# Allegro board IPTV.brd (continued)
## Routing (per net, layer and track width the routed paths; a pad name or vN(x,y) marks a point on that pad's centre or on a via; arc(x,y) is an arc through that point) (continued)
DDRB_DQ10: length 41.3
  TOP w0.127: IC13.B20 73.16,26.36 73.16,24.41
  TOP w0.152: U10.A7 55.33,10.21 55.52,10.02 57.08,10.02 v2(57.51,9.59) ; v1(71.43,15.89) 71.43,16.9 72.02,17.5 73.16,18.63 73.16,24.41
  BOTTOM w0.152: v2(57.51,9.59) 67.74,9.59 67.92,9.77 67.92,10.67 68.1,10.86 68.35,10.86 68.53,10.68 68.53,9.77 68.71,9.59 68.96,9.59 69.14,9.77 69.14,11.89 69.32,12.08 69.57,12.08 69.75,11.9 69.75,9.77 69.93,9.59 70.18,9.59 70.36,9.77 70.36,13.11 70.36,13.11 70.36,13.45 70.36,14.96 71.29,15.89 v1(71.43,15.89)
DDRB_DQ11: length 40.5
  TOP w0.127: 72.75,24.41 IC13.A20
  TOP w0.152: U10.D7 52.12,10.21 v2(52.52,10.61) ; 71.21,17.26 72.75,18.8 72.75,24.41 ; 71.21,17.26 71.49,17.54 ; 71.21,17.26 v1(70.46,16.51)
  BOTTOM w0.152: v2(52.52,10.61) 52.58,10.54 66.64,10.54 69.55,13.45 69.55,19.85 69.8,20.1 70.21,20.1 70.46,19.85 v1(70.46,16.51)
DDRB_DQ12: length 44.4
  TOP w0.127: 70.82,24.28 70.82,25 70.76,25.06 70.76,25.78 70.75,25.8 70.75,26.37 IC13.B23
  TOP w0.152: 70.82,24.28 70.82,19.6 66.32,15.1 64.29,15.1 64.11,14.92 64.11,14.03 63.93,13.85 63.68,13.85 63.5,14.03 63.5,14.92 63.32,15.1 63.07,15.1 62.89,14.92 62.89,14.03 62.71,13.85 61.65,13.85 61.47,14.03 61.47,14.92 61.29,15.1 61.04,15.1 60.86,14.92 60.86,14.03 60.68,13.85 59.61,13.85 59.44,14.03 59.44,14.95 59.28,15.1 58.98,15.1 58.83,14.95 58.83,13.25 58.59,13.01 57.64,13.01 57.4,13.25 57.4,16.63 57.4,18.68 57.15,18.94 56.39,18.94 56.13,18.68 56.13,13.78 55.77,13.41 U10.A3
DDRB_DQ13: length 44.4
  TOP w0.127: IC13.C23 69.96,27.18 69.96,25.65 70.01,25.61 70.01,24.28
  TOP w0.152: U10.A2 55.09,14.21 55.32,14.44 55.32,17.89 55.07,18.15 53.59,18.15 53.44,18.3 53.44,18.6 53.6,18.76 55.14,18.76 55.32,18.94 55.32,19.19 55.14,19.37 51.99,19.37 51.82,19.54 51.82,19.8 52,19.98 57.94,19.98 58.22,19.7 58.22,16.12 58.42,15.91 65.98,15.91 70.01,19.94 70.01,24.28
DDRB_DQ14: length 43
  TOP w0.102: U10.C3 53.32,13.82 55.36,13.82 55.55,14.01
  TOP w0.127: IC13.A23 70.42,25.9 70.42,24.28
  TOP w0.152: 70.42,24.28 70.42,19.77 66.15,15.51 62.71,15.51 62.48,15.28 62.48,14.44 62.31,14.26 62.05,14.26 61.87,14.44 61.87,15.33 61.7,15.51 60.63,15.51 60.45,15.33 60.45,14.44 60.27,14.26 60.02,14.26 59.84,14.44 59.84,15.33 59.66,15.51 58.6,15.51 58.42,15.33 58.42,13.57 58.27,13.42 57.96,13.42 57.81,13.57 57.81,16.8 57.81,19.32 57.56,19.57 55.96,19.57 55.73,19.34 55.73,14.19 55.55,14.01
DDRB_DQ15: length 44.2
  TOP w0.102: U10.C2 52.95,14.21 53.32,14.59 53.32,15.27
  TOP w0.127: IC13.C24 69.6,27.52 69.6,24.28
  TOP w0.152: 53.32,15.27 53.32,16.12 53.65,16.45 54.69,16.45 54.92,16.67 54.92,17.54 54.71,17.74 51.56,17.74 51.41,17.89 51.41,18.2 51.56,18.35 52.68,18.35 52.83,18.5 52.83,18.81 52.68,18.96 51.66,18.96 51.41,19.22 51.41,20.15 51.64,20.38 58.32,20.38 58.62,20.08 58.62,16.55 58.85,16.32 65.81,16.32 69.6,20.11 69.6,24.28
DDRB_DQSN0: length 44.8
  TOP w0.127: 74.89,24.31 74.85,24.35 74.85,25.2 74.76,25.29 74.76,27.73 74.35,28.14 IC13.D18
  TOP w0.152: 74.89,24.31 74.89,17.85 70.04,13 67.3,13 66.88,12.59 66.88,10.07 66.28,9.47 63.77,9.47 63.22,10.02 63.22,12.18 62.87,12.53 60.07,12.53 59.23,11.69 50.85,11.69 49.96,12.58 49.96,13.16 U10.G3
DDRB_DQSN1: length 41.8
  TOP w0.127: 72.14,24.31 72.14,27.1 71.95,27.29 IC13.C21
  TOP w0.152: v1(68.07,14.37) 67.84,14.59 67.84,14.75 72.14,19.06 72.14,24.31 ; v1(62.61,11.16) 62.38,11.39 61.87,11.39 61.64,11.17 61.64,10.98 61.42,10.76 61.11,10.76 60.88,10.98 60.88,11.17 60.66,11.39 60.22,11.39 59.61,10.78 53.56,10.78 53.37,10.58 53.37,10.35 53.5,10.21 U10.B7
  BOTTOM w0.152: v1(62.61,11.16) 62.84,11.39 63.17,11.39 63.49,11.71 63.49,13.73 63.71,13.96 64.02,13.96 64.25,13.73 64.25,11.56 64.65,11.16 65.22,11.16 65.62,11.56 65.62,13.73 65.84,13.96 66.16,13.96 66.38,13.73 66.38,12.73 66.78,12.33 67.46,12.33 67.84,12.71 67.84,14.14 v1(68.07,14.37)
DDRB_DQSP0: length 44.8
  TOP w0.127: IC13.C18 74.53,27.39 74.53,25.19 74.62,25.11 74.62,24.35 74.58,24.31
  TOP w0.152: U10.F3 50.27,13.16 50.27,12.71 50.98,11.99 59.1,11.99 59.95,12.84 62.99,12.84 63.53,12.3 63.53,10.15 63.9,9.77 66.15,9.77 66.57,10.2 66.57,12.71 67.17,13.31 69.92,13.31 70.21,13.6 70.21,13.91 69.67,14.45 69.67,14.77 69.89,14.99 70.21,14.99 70.75,14.45 71.06,14.45 74.58,17.97 74.58,24.31
DDRB_DQSP1: length 41.9
  TOP w0.127: 71.84,24.31 71.84,27.06 71.56,27.34 71.56,27.98 IC13.D21
  TOP w0.152: U10.C7 53.06,10.36 53.06,10.71 53.44,11.08 59.48,11.08 60.1,11.7 62.38,11.7 v1(62.61,11.92) ; 71.84,24.31 71.84,19.18 67.54,14.88 67.54,14.59 v1(67.31,14.37)
  BOTTOM w0.152: v1(67.31,14.37) 67.54,14.13 67.54,12.84 67.34,12.64 66.9,12.64 66.69,12.85 66.69,13.86 66.28,14.26 65.72,14.26 65.31,13.86 65.31,11.69 65.09,11.47 64.78,11.47 64.55,11.69 64.55,13.86 64.15,14.26 63.58,14.26 63.18,13.86 63.18,11.83 63.05,11.7 62.84,11.7 v1(62.61,11.92)
DDRB_ODT0: length 31.9
  TOP w0.152: R285.1 v1(49.67,28.07) ; v1(48.87,22.01) 48.87,21.63 48.11,20.87 48.11,16.81 47.31,16.02 U10.K1
  BOTTOM w0.152: v1(48.87,22.01) 48.87,22.31 49.07,22.52 52.6,22.52 52.78,22.69 52.78,23.76 52.6,23.94 48.59,23.94 48.41,24.12 48.41,24.37 48.59,24.55 52.55,24.55 52.81,24.8 52.81,27.82 52.56,28.07 v1(49.67,28.07)
DDRB_ODT0_R: length 7.4
  TOP w0.127: IC13.D35 60.35,27.96 59.32,27.96 58.89,27.96 58.63,27.7 58.54,27.61 57.06,27.61 57.02,27.64
  TOP w0.152: 57.02,27.64 56.6,28.07 R285.2
DDRB_RASN: length 33.8
  TOP w0.102: 48.51,16.64 48.51,13.81 U10.J3
  TOP w0.152: R274.1 49.33,29.21 v1(49,28.88) ; v1(49.51,22.01) 49.51,21.69 48.51,20.7 48.51,16.64
  BOTTOM w0.152: 49.33,22.01 v1(49.51,22.01) 53.68,22.01 53.87,22.2 53.87,22.61 53.7,22.78 53.38,22.78 53.21,22.95 53.21,23.24 53.38,23.41 53.7,23.41 53.87,23.59 53.87,23.84 53.7,24.02 53.38,24.02 53.21,24.18 53.21,24.43 53.41,24.63 53.7,24.63 53.87,24.8 53.87,25.06 53.7,25.24 53.38,25.24 53.21,25.4 53.21,25.65 53.41,25.85 53.7,25.85 53.87,26.02 53.87,26.28 53.7,26.46 53.38,26.46 53.21,26.62 53.21,26.87 53.41,27.06 53.7,27.06 53.87,27.24 53.87,27.5 53.7,27.67 53.38,27.67 53.21,27.84 53.21,28.09 53.41,28.28 53.7,28.28 53.87,28.46 53.87,28.71 53.7,28.89 49.01,28.89 v1(49,28.88)
DDRB_RASN_R: length 4.9
  TOP w0.152: IC13.D38 58.1,28.37 57.25,29.21 R274.2
DDRB_REF\G: length 11
  TOP w0.381: v2(66.75,34.37) 66.93,34.54 67.38,34.54 IC13.L26 ; IC13.L23 70.35,33.96 v2(69.95,33.56) ; IC13.L21 71.95,33.97 71.55,34.36 v2(71.55,34.36)
  BOTTOM w0.381: C314.2 R198.2 67.47,34.37 v2(66.75,34.37)
  BOTTOM w0.406: C314.2 69.22,33.82 C315.1 69.26,32.87 v2(69.95,33.56) 70.04,33.56 C309.2 70.74,33.55 v2(71.55,34.36) 71.6,34.32 R199.1
DDRB_RESETN\G: length 32
  BOTTOM w0.152: R636.1 R637.2 38.99,28.38 39.94,29.34 55.12,29.34 58.27,26.19 R193.2
DDRB_VREF_CA: length 10.8
  TOP w0.356: v2(46.11,9.81) U10.M8
  BOTTOM w0.508: R639.2 R640.1 50.75,6.2 C472.2 49.48,6.07 C471.1 C469.1 C470.1 46.11,6.08 v2(46.11,9.81)
DDRB_VREF_DQ: length 7.9
  TOP w0.356: U10.H1 48.91,15.01 v2(48.91,15.66)
  BOTTOM w0.508: R646.1 R634.2 C474.1 C475.1 C478.1 C481.2 48.91,15.85 v2(48.91,15.66)
DDRB_WEN: length 34.5
  TOP w0.152: U10.L3 46.92,13 48.49,13 v2(48.5,13) ; v1(62.59,18) 62.64,18.05 65.24,18.05 66.93,19.73 R279.1
  BOTTOM w0.152: v1(62.59,18) 62.59,17.16 62.33,16.9 59.03,16.9 58.74,16.61 58.74,13.18 58.56,13 58.31,13 58.13,13.18 58.13,17 57.95,17.18 57.7,17.18 57.52,17 57.52,13.26 57.26,13 54.45,13 53.95,13.5 52.96,13.5 52.46,13 v2(48.5,13)
DDRB_WEN_R: length 6
  TOP w0.152: R279.2 66.93,26.19 IC13.B28
DIFF_HDMI_0N\G: length 82.9
  TOP w0.152: XP1.9 44,118.02 arc(43.95,117.79) 43.83,117.6 arc(43.7,117.41) 43.65,117.18 43.65,114.31 arc(43.71,114.04) 43.86,113.81 v1(43.88,113.79) 43.79,113.7 arc(43.69,113.55) 43.65,113.37 arc(43.69,113.21) 43.78,113.07 44.11,112.73 arc(44.31,112.44) 44.37,112.1 44.37,109.38 arc(44.45,109) 44.67,108.67 60.19,93.15 arc(60.41,92.82) 60.48,92.44 60.48,91.99 arc(60.56,91.8) 60.75,91.73 60.96,91.73 arc(61.72,90.96) 60.96,90.2 60.75,90.2 arc(60.56,90.12) 60.48,89.93 60.48,89.75 arc(60.52,89.58) 60.62,89.43 61.48,88.57 61.79,88.26 71.44,78.61 arc(71.63,78.32) 71.7,77.97 71.7,55.65 arc(71.64,55.34) 71.47,55.08 IC13.AU22
  BOTTOM w0.152: U15.9 U15.2 41.59,112.39 arc(41.66,112.4) 41.71,112.44 arc(41.76,112.47) 41.83,112.48 43.03,112.48 arc(43.47,112.67) 43.65,113.11 43.65,113.56 arc(43.72,113.73) v1(43.88,113.79)
DIFF_HDMI_0P\G: length 82.3
  TOP w0.152: XP1.7 43,117.99 arc(43.05,117.76) 43.17,117.57 arc(43.3,117.38) 43.35,117.15 43.35,114.31 arc(43.29,114.04) 43.14,113.81 v1(43.12,113.79) 43.21,113.7 arc(43.31,113.55) 43.35,113.37 arc(43.4,113.09) 43.56,112.85 43.9,112.52 arc(44.02,112.33) 44.07,112.1 44.07,109.38 arc(44.17,108.88) 44.45,108.45 59.98,92.93 arc(60.13,92.71) 60.18,92.44 60.18,91.99 arc(60.35,91.59) 60.75,91.42 60.96,91.42 arc(61.42,90.96) 60.96,90.51 60.75,90.51 arc(60.35,90.34) 60.18,89.93 60.18,89.75 arc(60.24,89.46) 60.4,89.22 61.27,88.35 61.57,88.05 65.8,83.81 arc(65.9,83.67) 65.93,83.5 65.93,83.48 arc(65.97,83.27) 66.09,83.1 66.13,83.06 arc(66.27,82.96) 66.43,82.93 66.48,82.93 arc(66.67,82.89) 66.83,82.78 arc(66.93,82.64) 66.96,82.47 66.96,82.45 arc(67,82.24) 67.12,82.07 67.16,82.03 arc(67.3,81.93) 67.46,81.9 67.51,81.9 arc(67.7,81.86) 67.86,81.75 arc(67.96,81.61) 67.99,81.44 67.99,81.42 arc(68.03,81.21) 68.15,81.04 68.19,81 arc(68.33,80.9) 68.49,80.87 68.54,80.87 arc(68.73,80.83) 68.89,80.72 arc(68.99,80.58) 69.02,80.41 69.02,80.39 arc(69.06,80.18) 69.18,80.01 69.22,79.97 arc(69.36,79.87) 69.52,79.84 69.57,79.84 arc(69.76,79.8) 69.92,79.69 arc(70.02,79.55) 70.05,79.38 70.05,79.36 arc(70.09,79.15) 70.21,78.98 70.25,78.94 arc(70.39,78.84) 70.55,78.81 70.6,78.81 arc(70.79,78.77) 70.95,78.66 71.22,78.4 arc(71.35,78.2) 71.4,77.97 71.4,56.12 arc(71.34,55.84) 71.18,55.6 IC13.AV22
  BOTTOM w0.152: U15.10 U15.1 41.59,112.89 arc(41.66,112.87) 41.71,112.84 arc(41.76,112.8) 41.83,112.79 43.03,112.79 arc(43.25,112.88) 43.35,113.11 43.35,113.56 arc(43.28,113.73) v1(43.12,113.79)
DIFF_HDMI_1N\G: length 80.6
  TOP w0.127: IC13.AU23 70.53,54.94 arc(70.69,55.18) 70.74,55.46 70.74,55.72 arc(70.7,55.92) 70.59,56.09 arc(70.5,56.22) 70.47,56.37 70.47,56.76 70.48,56.77
  TOP w0.152: XP1.6 42.5,118.07 arc(42.45,117.84) 42.33,117.65 arc(42.2,117.46) 42.15,117.23 42.15,113.4 arc(42.21,113.13) 42.36,112.9 42.78,112.48 42.92,112.34 arc(43.09,112.08) 43.15,111.77 43.15,111.57 arc(42.98,111.16) 42.57,110.98 arc(42.51,110.97) 42.47,110.94 v1(42.28,110.76) 42.15,110.89 arc(42.01,110.98) 41.84,111.02 arc(41.75,110.98) 41.71,110.88 41.71,110.15 arc(41.77,109.83) 41.95,109.56 58.2,93.31 arc(58.8,92.41) 59.01,91.35 59.01,89.88 arc(59.28,88.53) 60.04,87.39 60.15,87.29 70.13,77.31 arc(70.39,76.91) 70.48,76.44 70.48,56.77
  BOTTOM w0.152: U15.6 U15.5 41.46,110.89 arc(41.53,110.9) 41.58,110.94 arc(41.64,110.97) 41.7,110.98 42.05,110.98 arc(42.21,110.92) v1(42.28,110.76)
DIFF_HDMI_1P\G: length 80.6
  TOP w0.127: IC13.AV23 70.35,55.86 arc(70.33,55.99) 70.25,56.1 arc(70.21,56.23) 70.19,56.37 70.19,56.74 70.18,56.75 70.18,56.77
  TOP w0.152: XP1.4 41.5,118.04 arc(41.55,117.81) 41.67,117.62 arc(41.8,117.43) 41.85,117.2 41.85,113.4 arc(41.92,113.01) 42.14,112.68 42.14,112.68 42.71,112.12 arc(42.81,111.96) 42.85,111.77 42.85,111.57 arc(42.77,111.37) 42.57,111.29 arc(42.51,111.3) 42.47,111.33 v1(42.28,111.52) 42.26,111.5 arc(42.07,111.37) 41.84,111.32 arc(41.53,111.19) 41.4,110.88 41.4,110.15 arc(41.49,109.71) 41.73,109.35 57.98,93.1 arc(58.52,92.29) 58.71,91.35 58.71,89.88 arc(59,88.42) 59.82,87.18 63.53,83.47 arc(63.64,83.31) 63.68,83.12 63.68,83.07 arc(63.71,82.91) 63.8,82.77 63.84,82.73 arc(64.02,82.61) 64.22,82.57 64.25,82.57 arc(64.42,82.54) 64.56,82.44 arc(64.67,82.28) 64.71,82.09 64.71,82.04 arc(64.74,81.88) 64.83,81.74 64.87,81.7 arc(65.05,81.58) 65.25,81.54 65.28,81.54 arc(65.45,81.51) 65.59,81.41 arc(65.7,81.25) 65.74,81.06 65.74,81.01 arc(65.77,80.85) 65.86,80.71 65.9,80.67 arc(66.08,80.55) 66.28,80.51 66.31,80.51 arc(66.48,80.48) 66.62,80.38 arc(66.73,80.22) 66.77,80.03 66.77,79.98 arc(66.8,79.82) 66.89,79.68 66.93,79.64 arc(67.11,79.52) 67.31,79.48 67.34,79.48 arc(67.51,79.45) 67.65,79.35 arc(67.76,79.19) 67.8,79 67.8,78.95 arc(67.83,78.79) 67.92,78.65 67.96,78.61 arc(68.14,78.49) 68.34,78.45 68.37,78.45 arc(68.54,78.42) 68.68,78.32 arc(68.79,78.16) 68.83,77.97 68.83,77.92 arc(68.86,77.76) 68.95,77.62 68.99,77.58 arc(69.17,77.46) 69.37,77.42 69.4,77.42 arc(69.57,77.39) 69.71,77.29 69.91,77.09 arc(70.11,76.79) 70.18,76.44 70.18,56.77
  BOTTOM w0.152: U15.7 U15.4 41.44,111.39 arc(41.5,111.37) 41.55,111.34 arc(41.61,111.3) 41.67,111.29 42.05,111.29 arc(42.21,111.36) v1(42.28,111.52)
DIFF_HDMI_2N\G: length 83
  TOP w0.127: 69.27,56.77 69.25,56.76 69.25,56.36 69.42,56.2 69.42,54.28 arc(69.46,54.11) IC13.AT24
  TOP w0.152: 69.27,56.77 69.27,73.95 arc(69.03,75.15) 68.35,76.16 67.12,77.39 arc(67.03,77.53) 66.99,77.7 66.99,77.73 arc(66.95,77.93) 66.84,78.11 66.8,78.15 arc(66.66,78.24) 66.49,78.27 66.45,78.27 arc(66.26,78.31) 66.09,78.42 arc(66,78.56) 65.96,78.73 65.96,78.76 arc(65.92,78.96) 65.81,79.14 65.77,79.18 arc(65.63,79.27) 65.46,79.3 65.42,79.3 arc(65.23,79.34) 65.06,79.45 arc(64.97,79.59) 64.93,79.76 64.93,79.79 arc(64.89,79.99) 64.78,80.17 64.74,80.21 arc(64.6,80.3) 64.43,80.33 64.39,80.33 arc(64.2,80.37) 64.03,80.48 arc(63.94,80.62) 63.9,80.79 63.9,80.82 arc(63.86,81.02) 63.75,81.2 63.71,81.24 arc(63.57,81.33) 63.4,81.36 63.36,81.36 arc(63.16,81.4) 63,81.51 arc(62.91,81.65) 62.87,81.82 62.87,81.85 arc(62.83,82.05) 62.72,82.23 62.68,82.27 arc(62.54,82.36) 62.37,82.39 62.33,82.39 arc(62.13,82.43) 61.97,82.54 57.86,86.65 arc(57.6,87.04) 57.51,87.51 57.51,88.61 arc(57.32,89.05) 56.89,89.23 56.71,89.23 arc(56.52,89.31) 56.44,89.5 56.44,89.87 arc(56.52,90.06) 56.71,90.14 56.88,90.14 arc(57.29,90.31) 57.46,90.72 57.46,91.78 arc(57.36,92.24) 57.11,92.63 40.87,108.87 arc(40.71,109.1) 40.65,109.38 40.65,116.7 arc(40.7,116.95) 40.85,117.17 v1(40.88,117.2) 40.77,117.31 arc(40.68,117.44) 40.65,117.59 arc(40.66,117.65) 40.69,117.69 40.86,117.86 arc(40.96,118.01) 41,118.2 XP1.3
  BOTTOM w0.152: U16.9 U16.2 41.66,115.79 arc(41.65,115.86) 41.62,115.91 arc(41.58,115.96) 41.57,116.03 41.57,116.17 arc(41.44,116.46) 41.15,116.59 40.8,116.59 arc(40.7,116.63) 40.65,116.74 40.65,116.97 arc(40.72,117.13) v1(40.88,117.2)
DIFF_HDMI_2P\G: length 83
  TOP w0.127: IC13.AR24 69.32,53.4 arc(69.19,53.6) 69.14,53.82 69.14,56.08 68.97,56.25 68.97,56.74 68.96,56.75 68.96,56.77
  TOP w0.152: XP1.1 40,118.25 arc(40.04,118.04) 40.16,117.87 40.29,117.74 arc(40.33,117.67) 40.35,117.59 arc(40.32,117.44) 40.23,117.31 v1(40.12,117.2) 40.15,117.17 arc(40.3,116.95) 40.35,116.7 40.35,109.38 arc(40.43,108.99) 40.65,108.65 56.89,92.41 arc(57.08,92.12) 57.15,91.78 57.15,90.72 arc(57.07,90.53) 56.88,90.45 56.71,90.45 arc(56.3,90.28) 56.13,89.87 56.13,89.5 arc(56.3,89.09) 56.71,88.92 56.89,88.92 arc(57.11,88.83) 57.2,88.61 57.2,87.51 arc(57.32,86.93) 57.65,86.44 68.14,75.94 arc(68.75,75.03) 68.96,73.95 68.96,56.77
  BOTTOM w0.152: U16.10 U16.1 41.16,115.82 arc(41.18,115.89) 41.21,115.94 arc(41.25,115.99) 41.26,116.06 41.26,116.17 arc(41.23,116.25) 41.15,116.28 40.8,116.28 arc(40.48,116.42) 40.35,116.74 40.35,116.97 arc(40.28,117.13) v1(40.12,117.2)
DIFF_HDMI_CLKN\G: length 84.7
  TOP w0.127: IC13.AR21 72.14,53.35 arc(72.29,53.58) 72.34,53.85 72.34,55.62 arc(72.38,55.77) 72.46,55.9 72.66,56.1 arc(72.85,56.37) 72.91,56.7 72.91,56.74 72.92,56.75 72.92,56.77
  TOP w0.152: 72.92,56.77 72.92,78.84 arc(72.82,79.37) 72.52,79.82 64.77,87.57 64.73,87.6 arc(64.54,87.9) 64.46,88.25 64.46,88.52 arc(64.3,88.92) 63.89,89.09 63.26,89.09 arc(63.07,89.17) 62.99,89.36 62.99,89.74 arc(63.07,89.93) 63.26,90 63.77,90 arc(64.17,90.17) 64.34,90.58 64.34,90.74 arc(64.27,91.08) 64.08,91.37 64,91.45 45.98,109.47 arc(45.73,109.84) 45.64,110.27 45.64,112.86 arc(45.58,113.16) 45.41,113.42 45.27,113.56 arc(45.18,113.69) 45.15,113.84 45.15,116.72 arc(45.2,116.95) 45.33,117.15 v1(45.38,117.2) 45.24,117.34 arc(45.15,117.56) 45.24,117.77 arc(45.43,118.06) 45.5,118.39 XP1.12
  BOTTOM w0.152: U16.6 U16.5 43.16,115.82 arc(43.15,115.89) 43.12,115.94 arc(43.08,115.99) 43.07,116.06 43.07,116.2 arc(43.11,116.31) 43.22,116.36 44.69,116.36 arc(45.02,116.49) 45.15,116.82 45.15,116.97 arc(45.22,117.13) v1(45.38,117.2)
DIFF_HDMI_CLKP\G: length 84.6
  TOP w0.127: 72.62,56.77 72.62,56.75 72.63,56.74 72.63,56.7 arc(72.59,56.48) 72.47,56.3 72.26,56.09 arc(72.12,55.88) 72.07,55.62 72.07,54.24 arc(72.04,54.09) IC13.AT21
  TOP w0.152: XP1.10 44.5,118.35 arc(44.58,117.98) 44.79,117.66 arc(44.85,117.51) 44.79,117.37 v1(44.62,117.2) 44.67,117.15 arc(44.8,116.95) 44.85,116.72 44.85,113.84 arc(44.9,113.57) 45.06,113.34 45.2,113.2 arc(45.3,113.04) 45.34,112.86 45.34,110.27 arc(45.45,109.72) 45.76,109.26 63.79,91.23 63.86,91.16 arc(63.99,90.96) 64.03,90.74 64.03,90.58 arc(63.95,90.39) 63.77,90.31 63.26,90.31 arc(62.86,90.14) 62.69,89.74 62.69,89.36 arc(62.86,88.95) 63.26,88.79 63.89,88.79 arc(64.08,88.71) 64.16,88.52 64.16,88.25 arc(64.25,87.78) 64.52,87.39 66.95,84.96 arc(67.06,84.79) 67.09,84.6 67.09,84.56 arc(67.13,84.39) 67.22,84.25 67.26,84.21 arc(67.43,84.1) 67.64,84.06 67.67,84.06 arc(67.83,84.02) 67.98,83.93 arc(68.09,83.76) 68.12,83.57 68.12,83.53 arc(68.16,83.36) 68.25,83.22 68.29,83.18 arc(68.46,83.07) 68.67,83.03 68.7,83.03 arc(68.86,82.99) 69.01,82.9 arc(69.12,82.73) 69.15,82.54 69.15,82.5 arc(69.19,82.33) 69.28,82.19 69.32,82.15 arc(69.49,82.04) 69.7,82 69.73,82 arc(69.9,81.96) 70.04,81.87 arc(70.15,81.7) 70.18,81.51 70.19,81.47 arc(70.22,81.3) 70.31,81.16 70.35,81.12 arc(70.52,81.01) 70.73,80.96 70.76,80.96 arc(70.93,80.93) 71.07,80.84 arc(71.18,80.67) 71.21,80.48 71.22,80.44 arc(71.25,80.27) 71.34,80.13 71.38,80.09 arc(71.56,79.98) 71.76,79.93 71.79,79.93 arc(71.96,79.9) 72.1,79.81 72.3,79.6 arc(72.54,79.25) 72.62,78.84 72.62,56.77
  BOTTOM w0.152: U16.7 U16.4 42.66,115.92 arc(42.68,115.98) 42.71,116.04 arc(42.75,116.09) 42.76,116.15 42.76,116.2 arc(42.9,116.53) 43.22,116.66 44.69,116.66 arc(44.8,116.71) 44.85,116.82 44.85,116.97 arc(44.78,117.13) v1(44.62,117.2)
DIFF_USB0D_N\G: length 135.7
  TOP w0.127: 66.19,56.21 66.19,55.96 65.96,55.73 65.96,55.16 IC13.AU28
  TOP w0.203: 66.19,56.21 66.19,57.52 65.91,57.8 65.91,63.86 arc(65.82,64.07) 65.61,64.15 arc(65.47,64.09) v1(65.41,63.95) ; v1(86.69,63.95) arc(86.89,64.08) 87.12,64.12 87.4,64.12 arc(87.87,64.22) 88.27,64.48 88.77,64.98 arc(89.14,65.23) 89.57,65.32 139.12,65.32 arc(139.66,65.21) 140.11,64.9 141.86,63.16 arc(142.22,62.62) 142.34,61.99 142.34,32.52 arc(142.5,31.73) 142.95,31.05 148.13,25.87 arc(148.86,25.38) 149.73,25.21 155.14,25.21 arc(155.45,25.08) R630.2
  BOTTOM w0.203: v1(65.41,63.95) arc(65.6,64.08) 65.83,64.12 86.26,64.12 arc(86.49,64.08) v1(86.69,63.95)
DIFF_USB0D_P\G: length 135.3
  TOP w0.203: IC13.AV28 66.6,55.81 66.6,57.69 66.32,57.97 66.32,63.86 arc(66.11,64.35) 65.61,64.56 65.55,64.56 arc(65.45,64.6) v1(65.41,64.71) ; v1(86.69,64.71) arc(86.89,64.58) 87.12,64.53 87.4,64.53 arc(87.72,64.59) 87.99,64.77 88.49,65.27 arc(88.98,65.6) 89.57,65.72 139.12,65.72 arc(139.81,65.58) 140.4,65.19 142.15,63.44 arc(142.59,62.78) 142.75,61.99 142.75,32.52 arc(142.88,31.88) 143.24,31.34 148.42,26.16 arc(149.02,25.76) 149.73,25.62 155.14,25.62 arc(155.45,25.74) R621.2
  BOTTOM w0.203: v1(65.41,64.71) arc(65.6,64.58) 65.84,64.53 86.26,64.53 arc(86.49,64.58) v1(86.69,64.71)
EBI_DQ0\G: length 24.6
  TOP w0.152: IC13.Y1 88.62,41.17 89.42,40.36 102.4,40.36 v1(103.48,39.28)
  BOTTOM w0.152: v1(103.48,39.28) 103.48,34.71 105.45,32.74 IC2.29
EBI_DQ1\G: length 24.7
  TOP w0.127: 89.41,40.06 89.29,40.06 88.58,40.77 87.55,40.77 IC13.Y2
  TOP w0.152: v1(102.72,39.28) 101.94,40.06 89.41,40.06
  BOTTOM w0.152: IC2.30 104.95,32.6 103.1,34.45 103.1,38.9 v1(102.72,39.28)
EBI_DQ2\G: length 23
  TOP w0.152: v1(101.96,39.28) 101.48,39.75 99.14,39.75 89.17,39.75 88.55,40.37 IC13.W1
  BOTTOM w0.152: IC2.31 104.45,32.48 101.96,34.97 v1(101.96,39.28)
EBI_DQ3\G: length 23
  TOP w0.127: IC13.W2 87.54,39.98 88.51,39.98 89.04,39.45 89.41,39.45
  TOP w0.152: 89.41,39.45 100.77,39.45 v1(100.94,39.28)
  BOTTOM w0.152: IC2.32 103.95,32.55 100.94,35.56 v1(100.94,39.28)
EBI_DQ4\G: length 21
  TOP w0.127: IC13.W3 86.6,40.37 87.24,39.72 88.35,39.72 88.93,39.14 89.41,39.14
  TOP w0.152: v1(99.67,38.65) 99.17,39.14 89.41,39.14
  BOTTOM w0.152: v1(99.67,38.65) 99.45,38.43 IC2.41
EBI_DQ5\G: length 20.9
  TOP w0.127: IC13.W4 85.96,39.96 86.55,39.96 87.07,39.44 88.23,39.44 88.83,38.84 89.41,38.84
  TOP w0.152: 89.41,38.84 98.72,38.84 v1(98.95,38.6)
  BOTTOM w0.152: v1(98.95,38.6) 98.95,38.6 IC2.42
EBI_DQ6\G: length 19
  TOP w0.127: IC13.V3 86.56,39.57 86.97,39.16 88.11,39.16 88.74,38.53 89.41,38.53
  TOP w0.152: v1(98.45,38.09) 98.01,38.53 89.41,38.53
  BOTTOM w0.152: IC2.43 v1(98.45,38.09)
EBI_DQ7\G: length 19.3
  TOP w0.127: IC13.V4 85.94,39.18 86.5,39.18 86.74,38.93 86.74,38.6 86.99,38.36 88.11,38.36 88.24,38.23 89.41,38.23
  TOP w0.152: v1(97.64,38.07) 97.49,38.23 89.41,38.23
  BOTTOM w0.152: v1(97.64,38.07) 97.95,37.76 IC2.44
ENET_ACTIVITY_LEDB\G: length 48.4
  TOP w0.152: v1(89.13,53.39) 88.17,53.39 IC13.AR1 ; R271.1 v1(105.89,15.4)
  BOTTOM w0.152: v1(105.89,15.4) 94.72,26.58 94.72,47.46 94.72,47.46 94.72,48.62 94.72,48.62 94.72,50.08 91.4,53.39 v1(89.13,53.39)
ENET_IND\G: length 45.8
  TOP w0.127: v2(89.13,52.78) 87.54,52.78 IC13.AR2
  TOP w0.152: R355.2 v1(102.72,16.93)
  BOTTOM w0.152: v2(89.13,52.78) 91.38,52.78 94.41,49.75 94.41,48.5 94.41,25.23 v1(102.72,16.93)
ETH_RSTN\G: length 47.5
  TOP w0.152: v1(47.85,86.91) 52.05,86.91 52.81,86.14 52.81,83.37 59.06,77.13 R366.1 59.03,62.62 R364.2 ; R315.2 v1(34.42,88.56)
  BOTTOM w0.152: v1(34.42,88.56) 37.06,88.56 38.2,87.41 47.35,87.41 v1(47.85,86.91)
FE0_DUPLEX: length 40
  TOP w0.152: IC8.16 20.95,80.81 R311.2 21.22,78.87 23.57,76.52 29.64,76.52 35.38,70.77 35.38,68.67 38.23,65.83 38.23,63.84 43.21,58.86 44.66,58.86 46.48,57.04 R132.2
FUNSEL\G: length 6.9
  TOP w0.127: IC13.C13 78.57,27.57 79.56,26.58 79.78,26.36 80.11,26.36 80.34,26.13 80.34,25.82 80.49,25.67 80.49,24.28
  TOP w0.152: R230.1 80.49,24.28
HDMI_CEC\G: length 78.3
  TOP w0.152: XP1.13 v1(46,116.5) ; v1(47.42,109.51) 65.4,91.53 65.4,88.41 73.85,79.97 73.85,56.67 IC13.AV20
  BOTTOM w0.152: v1(46,116.5) 44.58,115.07 44.58,110.1 44.88,109.79 U14.1 47.14,109.79 v1(47.42,109.51)
HDMI_HOT_PLUG\G: length 79.7
  TOP w0.152: IC13.AT19 74.3,54.71 74.3,55.56 75.42,56.68 75.42,80.58 66.95,89.05 66.95,92.49 51.18,108.27 v1(51.18,109.8) R146.1 51.16,110.64 C247.1 51.16,112.02 D20.3 51.16,114.95 49,117.12 XP1.19
  BOTTOM w0.152: v1(51.18,109.8) 51.17,109.79 U14.6
I2C3_SCL\G: length 9.6
  TOP w0.127: IC13.AB2 87.54,42.38 88.49,42.38 88.75,42.63 88.88,42.63
  TOP w0.152: 88.88,42.63 89.66,42.63 90.42,43.4 C178.1 90.42,43.81 90.65,44.04 R59.2 93.09,43.76 93.38,43.47 R38.1
I2C3_SDA\G: length 7.4
  TOP w0.152: IC13.AC1 89.63,45.25 R62.2 90.88,45.83 91.89,45.83 v1(91.9,45.85) 91.94,45.88 R37.1
  BOTTOM w0.152: C72.1 91.23,46.52 v1(91.9,45.85)
IR_IN\G: length 84.3
  TOP w0.127: v2(81.19,26.33) 81.19,26.88 80.91,27.16 80.36,27.16 IC13.C11
  TOP w0.152: v1(135.4,9.99) 137.82,9.99 143.36,4.45 R119.2 144.96,4.39 D37.1
  BOTTOM w0.152: v1(135.4,9.99) 132.37,9.99 130.4,11.95 103.37,11.95 102.07,13.25 93.45,13.25 92.56,14.13 92.56,19.47 91.29,20.74 88.37,20.74 87.48,21.63 87.48,26.71 87.1,27.09 83.41,27.09 82.65,26.33 v2(81.19,26.33)
IR_LED_INDIC\G: length 85.3
  TOP w0.152: IC13.AP2 88.05,51.47 v2(89.13,51.47) ; v1(97.64,19.85) 97.64,7.78 98.02,7.4 130.29,7.4 LED12.2
  BOTTOM w0.152: v1(97.64,19.85) 97.64,20.59 93.8,24.42 93.8,47.84 93.8,47.84 93.8,48.24 93.8,48.24 93.8,49.49 91.82,51.47 v2(89.13,51.47)
JTAG_SEL\G: length 93.5
  TOP w0.127: 84.07,55.69 84.35,55.97 84.35,56.77
  TOP w0.152: R81.1 v1(33.27,115.19) ; 84.07,55.69 IC13.AU7 ; 84.35,56.77 R46.1 R45.1 84.35,81.38 v1(73.53,92.2)
  BOTTOM w0.152: v1(73.53,92.2) 65.59,92.2 52.45,105.35 44.2,105.35 34.35,115.19 v1(33.27,115.19)
LED0_LINK_ACT\G: length 1.7
  TOP w0.152: R130.2 R114.1
LED_WLAN: length 2.3
  TOP w0.152: LED8.2 115.09,48.3 R349.2
LNA_CORE_VDD1P2: length 7
  TOP w0.203: v1(123.89,40.65) 124.04,40.8 U18.27 ; U18.23 122.44,40.74 v1(122.52,40.65)
  BOTTOM w0.406: 122.52,41.44 123.55,41.44 123.89,41.1 v1(123.89,40.65) 124.56,39.98 C322.1 ; 122.52,41.44 FB1.1 ; 122.52,41.44 v1(122.52,40.65) 122.02,40.16 C320.1
LOGEN_VDD1P2: length 3
  TOP w0.203: v1(123.18,40.65) 123.18,40.82 123.64,41.27 U18.26
  TOP w0.406: C355.2 123.42,40.07 123.18,40.31 v1(123.18,40.65)
  BOTTOM w0.406: C355.2 123.42,40.07 123.18,40.31 v1(123.18,40.65)
MDCK\G: length 50
  TOP w0.152: IC8.12 20.44,83.05 v1(20.19,82.8) ; R242.2 54.3,59.28 52.9,60.69 43.97,60.69 40.06,64.6 40.06,66.59 37.21,69.43 37.21,71.53 30.1,78.65 v1(27.79,78.65)
  BOTTOM w0.152: v1(20.19,82.8) 20.19,80.78 20.89,80.09 26.35,80.09 v1(27.79,78.65)
MDIO\G: length 55.4
  TOP w0.152: IC13.AU38 57.53,55.59 57.53,56.27 56.85,56.96 R233.1 56.85,57.59 56.62,57.82 55.33,57.82 52.77,60.39 43.84,60.39 39.75,64.48 39.75,66.46 36.91,69.31 36.91,71.41 30.12,78.19 v1(28.55,78.19) ; IC8.11 v1(20.2,83.55)
  BOTTOM w0.152: v1(20.2,83.55) 20.83,82.93 20.83,81.33 21.77,80.39 26.81,80.39 28.55,78.65 v1(28.55,78.19)
MUTE_CTL\G: length 98.3
  TOP w0.127: IC13.C5 85.14,27.18 88.41,27.18 88.62,26.96 88.65,26.96
  TOP w0.381: v1(95.17,26.83) 88.78,26.83 88.65,26.96 ; v1(85.34,60.33) 85.32,60.35 85.32,82.08 77.83,89.57 R88.1
  BOTTOM w0.381: v1(85.34,60.33) 93.94,60.33 95.17,59.09 v1(95.17,26.83)
NF_ADNUM\G: length 6.5
  TOP w0.152: R236.1 R227.1 54.73,55.24 56.61,55.24 57.76,54.08 59.03,54.08 IC13.AT37
NF_ALE\G: length 22.7
  TOP w0.152: v1(102.97,40.67) 93.2,40.67 92.57,41.3 92.11,41.3 92,41.19 R57.1
  BOTTOM w0.152: v1(102.97,40.67) 102.97,47.7 103.95,48.68 IC2.17
NF_BLKSIZE\G: length 5
  TOP w0.152: R242.1 R224.1 57.15,57.8 59.15,55.8 IC13.AV37
NF_BOOTBW\G: length 10.4
  TOP w0.127: IC13.AA3 86.5,41.82 88.88,41.82 88.94,41.76 89.41,41.76
  TOP w0.152: R41.1 93.22,41.19 93.09,41.31 R63.2 v1(92.43,41.76) 89.41,41.76
  BOTTOM w0.152: R42.1 92.39,41.72 v1(92.43,41.76)
NF_CLE\G: length 16.9
  TOP w0.152: v1(102.34,42.9) R58.1
  BOTTOM w0.152: IC2.16 103.45,49.16 102.34,48.04 v1(102.34,42.9)
NF_CSN0\G: length 23.1
  TOP w0.127: 89.41,44.37 88.22,43.18 86.76,43.18 IC13.AB3
  TOP w0.152: v1(99.95,45.25) 99.16,45.25 98.86,44.94 92,44.94 91.71,44.65 89.69,44.65 89.41,44.37
  BOTTOM w0.152: v1(99.95,45.25) IC2.9 99.95,53.41 R98.1
NF_CSN1\G: length 19.3
  TOP w0.152: v1(101.45,56.04) 100.41,55.01 100.41,44.66 99.8,44.04 R59.1
  BOTTOM w0.152: R143.2 v1(101.45,56.04)
NF_PAGE0\G: length 10
  TOP w0.127: 57.31,54.1 57.6,53.81 58.76,53.81 58.99,53.58 59.54,53.58 IC13.AR36
  TOP w0.152: R235.1 R228.1 52.27,55.28 52.62,54.93 56.48,54.93 57.02,54.39 57.31,54.1
NF_PAGE1\G: length 11.3
  TOP w0.127: IC13.AR37 58.9,53.17 58.51,53.56 57.42,53.56 57.02,53.96
  TOP w0.152: R234.1 R225.1 50.11,55.28 50.77,54.63 56.35,54.63 57.02,53.96
NF_RDY0\G: length 18.6
  TOP w0.152: v1(97.01,47.15) 92.59,47.15 91.88,46.44 91.26,46.44 90.96,46.14 89.72,46.14 IC13.AC2
  BOTTOM w0.152: v1(97.01,47.15) 98.95,49.09 IC2.7 98.95,53.59 R97.1
NF_RDY1\G: length 17.5
  TOP w0.152: v1(97.64,56.17) 97.64,46.65 96.24,45.25 R62.1
  BOTTOM w0.152: R142.2 v1(97.64,56.17)
NF_REN\G: length 18.7
  TOP w0.127: 89.41,43.93 88.24,42.77 IC13.AB1
  TOP w0.152: v1(99.45,44.64) 92.13,44.64 91.83,44.35 89.82,44.35 89.41,43.93
  BOTTOM w0.152: v1(99.45,44.64) IC2.8
NF_WEN\G: length 19.1
  TOP w0.152: R63.1 v1(103.43,41.76)
  BOTTOM w0.152: IC2.18 104.45,48.17 103.43,47.15 v1(103.43,41.76)
NF_WP\G: length 2.7
  BOTTOM w0.152: IC2.19 104.95,52.31 105.26,52.62 R139.2
NFC_ECC0\G: length 4.9
  TOP w0.127: IC13.B2 87.56,26.36 88.3,26.36 88.6,26.05
  TOP w0.152: 88.6,26.05 88.71,25.95 R297.1 R293.1
NFC_ECC1\G: length 3
  TOP w0.152: R223.1 R295.1 88.11,25.01 IC13.A2
NFC_ECC2\G: length 5.2
  TOP w0.127: IC13.D1 88.56,28.37 88.8,28.61 88.8,28.99
  TOP w0.152: R229.1 89.51,30.26 89.41,30.16 R222.1 89.26,29.76 88.8,29.3 88.8,28.99
PCIE_CLKOUTN: length 67.4
  TOP w0.152: v1(109.3,59.6) 109.4,59.5 109.4,35.34 105.3,31.24 95.31,31.24 93.28,33.27 92.93,33.27 v1(92.7,33.5) 92.48,33.27 92.19,33.27 R66.2 ; v1(123.5,58.53) 123.66,58.69 123.92,58.69 124.18,58.42 124.18,53.35 C194.2
  BOTTOM w0.152: v1(123.5,58.53) 123.33,58.71 109.78,58.71 109.4,59.09 109.4,59.5 v1(109.3,59.6) ; v1(92.7,33.5) 92.48,33.27 92.19,33.27 R66.2
PCIE_CLKOUTP: length 68.3
  TOP w0.152: R65.2 92.19,32.97 92.48,32.97 v1(92.7,32.74) 92.93,32.97 93.16,32.97 95.19,30.94 105.42,30.94 109.7,35.22 109.7,59.37 v1(109.93,59.6) ; C193.2 124.49,53.43 124.49,58.55 124.04,58.99 123.67,58.99 123.5,59.16 v1(123.5,59.3)
  BOTTOM w0.152: v1(123.5,59.3) 123.5,59.15 123.37,59.02 109.91,59.02 109.7,59.22 109.7,59.37 v1(109.93,59.6) ; R65.2 92.19,32.97 92.48,32.97 v1(92.7,32.74)
PCIE_CLKREQ: length 45.8
  TOP w0.152: R323.2 R354.2 98.68,34.68 98.78,34.58 100.81,34.58 100.97,34.73 R94.1 101.48,35.6 v1(103.99,35.6) ; R319.2 v1(128.37,53.76)
  BOTTOM w0.152: v1(128.37,53.76) 128.22,53.61 112.42,53.61 104.39,45.58 104.39,38.2 103.99,37.8 v1(103.99,35.6)
PCIE_RDN: length 70.8
  TOP w0.127: IC13.M4 85.63,34.77 86.04,35.17 88.44,35.17 89.01,34.59 89.4,34.59 89.41,34.61
  TOP w0.152: 89.41,34.61 93.74,34.61 95.88,32.46 104.75,32.46 107.85,35.56 107.85,60.29 110.13,62.57 119.23,62.57 122.31,59.49 122.31,55.47 R339.2
PCIE_RDP: length 70.8
  TOP w0.127: 89.41,34.3 89.39,34.3 89.38,34.31 88.88,34.31 88.32,34.88 86.46,34.88 IC13.M3
  TOP w0.152: R337.2 121.84,55.13 122.01,55.29 122.01,56.74 121.81,56.95 121.4,56.95 121.23,57.11 121.23,57.54 121.4,57.71 121.88,57.71 122.01,57.83 122.01,59.36 119.1,62.27 110.26,62.27 108.15,60.16 108.15,35.43 104.88,32.16 95.76,32.16 93.61,34.3 89.41,34.3
PCIE_RST: length 42
  TOP w0.152: R328.2 R106.2 98.68,36.97 98.83,36.82 100.76,36.82 100.97,37.02 R96.1 100.97,38.01 101.35,38.39 v1(103.94,38.39) ; R341.2 v1(126.09,54.06)
  BOTTOM w0.152: v1(103.94,38.39) 103.94,45.55 112.45,54.06 v1(126.09,54.06)
PCIE_TDN: length 55
  TOP w0.152: C358.1 92.21,35.65 93.9,35.65 96.16,33.39 104.37,33.39 106.66,35.67 106.66,56.32 v1(106.88,56.55) ; R347.2 119.65,55.55 119.65,55.84 v1(119.42,56.06)
  BOTTOM w0.152: v1(106.88,56.55) 106.66,56.78 106.66,56.93 106.82,57.1 117.47,57.1 117.69,56.87 117.69,56.37 117.91,56.15 118.23,56.15 118.45,56.37 118.45,56.87 118.68,57.1 119.41,57.1 119.65,56.86 119.65,56.29 v1(119.42,56.06)
PCIE_TDP: length 54.1
  TOP w0.152: v1(120.18,56.06) 119.95,55.84 119.95,55.55 R343.2 ; C359.1 92.17,35.96 94.03,35.96 96.29,33.69 104.24,33.69 106.35,35.8 106.35,56.32 v1(106.12,56.55)
  BOTTOM w0.152: v1(106.12,56.55) 106.35,56.78 106.35,57.06 106.69,57.4 119.53,57.4 119.95,56.98 119.95,56.29 v1(120.18,56.06)
PCIE_WAKE_L: length 7.1
  TOP w0.152: R324.2 101.24,36.79 100.97,36.51 R91.1 100.97,35.88 100.76,35.67 98.83,35.67 98.68,35.83 R93.2 R325.2
PHY0_AD1: length 3.6
  TOP w0.152: IC8.14 20.59,82.05 R312.2 R313.2
POWER_LED_INDIC\G: length 71.4
  TOP w0.152: v2(89.13,52.11) 88.21,52.11 IC13.AP1 ; R457.1 v1(125.98,12.41)
  BOTTOM w0.152: v2(89.13,52.11) 91.62,52.11 94.11,49.62 94.11,48.37 94.11,24.57 106.27,12.41 v1(125.98,12.41)
RESET_DDR3\G: length 4.5
  BOTTOM w0.152: R637.1 R648.2 R647.2 38.99,20.73 R620.1
RESET_SYS\G: length 161.8
  TOP w0.127: IC13.C6 83.95,25.41 84.18,25.18 84.18,24.28
  TOP w0.152: v1(29.19,75.35) 29.3,75.35 34.47,70.18 34.47,68.29 37.31,65.45 37.31,56.1 29.57,48.35 29.57,35.55 36.93,28.18 36.93,23.3 v1(37.47,22.77) 37.47,22.11 38.2,21.37 38.2,6.25 40.6,3.85 v1(72.11,3.85) ; R20.2 v1(77.32,14.64) 77.32,15.45 80.82,18.96 81.76,18.96 82.02,19.21 C338.1 82.65,20.87 83.8,20.87 84.18,21.25 84.18,24.28 ; R316.2 v1(33.02,88.65)
  BOTTOM w0.152: R647.1 v1(37.47,22.77) ; v1(72.11,3.85) 72.11,4.61 77.32,9.82 v1(77.32,14.64) ; v1(33.02,88.65) 33.02,79.18 v1(29.19,75.35)
RF_DISABLE_N: length 70
  TOP w0.152: v1(127.23,54.52) R332.2 ; R327.2 R102.2 R99.1 100.81,22.01 111.86,33.06 111.86,40.3 111.74,40.42 111.74,42.51 112.83,43.6 v1(112.83,54.52)
  BOTTOM w0.152: v1(127.23,54.52) v1(112.83,54.52)
ROMBOOT_SEL\G: length 5.5
  TOP w0.127: IC13.D9 81.96,27.96 81.96,25.79 82.07,25.67
  TOP w0.152: R47.1 R48.1 82.53,25.22 82.35,25.39 82.35,25.4 82.07,25.67
RX+_PHY0\G: length 16.9
  TOP w0.152: TR2.6 28.02,96.9 29.54,95.38 29.54,94.23 27.66,92.35 24.83,92.35 v1(24.57,92.61) 24.34,92.38 24,92.38 23.7,92.07 23.7,91.06 24.21,90.55 24.21,90.09 R127.2
  BOTTOM w0.152: R309.1 25.81,92.35 24.83,92.35 v1(24.57,92.61) U17.3
RX-_PHY0\G: length 16.9
  TOP w0.152: R126.2 24.51,90.02 24.51,90.68 24,91.19 24,91.95 24.13,92.08 24.29,92.08 v1(24.57,91.8) 24.83,92.05 27.79,92.05 29.84,94.11 29.84,95.38 31.37,96.9 TR2.8
  BOTTOM w0.152: R303.1 25.81,92.05 24.83,92.05 v1(24.57,91.8) U17.4
RXD0_RMII0: length 13.7
  TOP w0.127: IC13.AP37 58.74,52.78 57.34,52.78 57.03,53.08
  TOP w0.152: 57.03,53.08 56.1,54.02 47.2,54.02 R132.1
RXD1_RMII0: length 14.1
  TOP w0.152: IC13.AP38 57.32,52.37 55.97,53.71 46.24,53.71 R154.1
RXDV_RMII0: length 11.3
  TOP w0.152: R302.1 48.17,54.32 56.23,54.32 57.38,53.17 IC13.AR38
RXG_0: length 2.5
  TOP w0.254: C238.1 U21.3
RXG_1: length 1.5
  TOP w0.254: C334.1 121.9,32.45 U19.1
SD_CCLK_OUT: length 52
  TOP w0.127: IC13.AU34 61.15,55.17 61.15,55.82 60.2,56.77
  TOP w0.152: v1(59.77,60.9) 59.77,60.39 59.41,60.02 59.41,57.56 60.2,56.77 ; U12.5 v1(25.4,46.12)
  BOTTOM w0.152: v1(25.4,46.12) 26.85,47.57 26.85,51.5 33.81,58.46 56.49,58.46 57.61,59.57 57.61,60.49 58.01,60.9 v1(59.77,60.9)
SD_CCMD: length 51.1
  TOP w0.152: v1(25.53,38.61) 25.54,38.62 U12.2 ; R239.2 v1(58.42,59.96)
  BOTTOM w0.152: v1(58.42,59.96) 58.22,59.75 58.22,59.32 56.74,57.85 34.06,57.85 27.46,51.25 27.46,40.54 v1(25.53,38.61) R149.1
SD_CDATA0: length 44
  TOP w0.152: U12.7 25.4,51.05 v1(25.4,51.05) ; v1(60.55,60.9) 61.06,60.39 R160.2
  BOTTOM w0.152: R150.1 v1(25.4,51.05) 25.97,51.05 33.68,58.76 55.27,58.76 57.89,61.38 60.07,61.38 v1(60.55,60.9)
SD_CDATA1: length 45.7
  TOP w0.152: v1(62.08,60.74) 62.2,60.74 63.35,59.6 R296.2 ; U12.8 25.32,52.75 v1(25.27,52.7)
  BOTTOM w0.152: R151.1 v1(25.27,52.7) 27.19,52.7 33.55,59.07 55.14,59.07 57.76,61.68 61.42,61.68 62.08,61.02 v1(62.08,60.74)
SD_CDATA2: length 59.1
  TOP w0.152: v1(25.53,33.66) 25.56,33.62 U12.9 ; R238.2 v1(62.21,59.85)
  BOTTOM w0.152: R147.1 v1(25.53,33.66) 28.07,36.2 28.07,50.99 34.31,57.24 57.5,57.24 59.5,59.24 61.6,59.24 v1(62.21,59.85)
SD_CDATA3: length 55.1
  TOP w0.152: v1(25.53,36.07) 25.4,36.07 25.45,36.12 U12.1 ; R237.2 59.92,59.89 v1(59.97,59.93)
  BOTTOM w0.152: v1(59.97,59.93) 59.76,59.93 57.37,57.54 34.19,57.54 27.76,51.12 27.76,38.3 v1(25.53,36.07) R148.1
SD_CWPR: length 37.2
  TOP w0.152: v1(52.81,59.52) 55.09,57.24 55.09,56.04 55.38,55.75 R241.2 ; U12.11 v1(25.38,56.1)
  BOTTOM w0.152: v1(52.81,59.52) 33.58,59.52 29.17,55.12 R152.1 25.37,56.1 v1(25.38,56.1)
SD_DETECT: length 54.8
  TOP w0.152: R292.2 61.8,61.35 v1(61.32,60.87) ; U12.10 v1(25.54,40.27)
  BOTTOM w0.152: v1(61.32,60.87) 60.88,60.44 58.25,60.44 57.91,60.1 57.91,59.45 56.62,58.15 33.93,58.15 27.15,51.37 27.15,41.88 v1(25.54,40.27) 25.53,40.26 R153.1
SD_POWER_EN: length 73.1
  BOTTOM w0.152: R294.2 59.63,58.94 57.62,56.93 34.44,56.93 28.37,50.87 28.37,32.24 24.23,28.1 R166.2 R164.2
SELF_BOOT\G: length 6.1
  TOP w0.127: 81.9,24.28 81.89,24.29
  TOP w0.152: R43.1 81.92,24.27 81.9,24.28 ; 81.89,24.29 81.79,24.4 R44.1 81.38,25.94 81.6,26.16 81.6,27.52 IC13.C9
SFC_CLK\G: length 12.7
  TOP w0.152: R64.2 TP1.1 94.72,53.9 92.46,56.16 U11.6
SFC_CSN1: length 10
  TOP w0.127: 89.13,47.87 88.37,47.87 88.26,47.98 87.54,47.98 IC13.AJ2
  TOP w0.152: 89.13,47.87 v1(89.92,47.87) ; v1(89.92,53.99) U11.1 v1(89.92,50.1)
  BOTTOM w0.152: v1(89.92,50.1) v1(89.92,47.87) ; R167.1 v1(89.92,53.99)
SFC_DIO: length 12.1
  TOP w0.127: v2(88.65,49.66) 88.56,49.57 86.75,49.57 IC13.AK3
  BOTTOM w0.152: v2(88.65,49.66) 88.65,54.75 90.32,56.43 R157.2
SFC_DOI: length 4.9
  TOP w0.127: v1(88.9,47.2) 88.86,47.15 87.56,47.15 IC13.AH2
  BOTTOM w0.152: v1(88.9,47.2) 90.44,47.2 91.16,47.92 R112.1
SFC_HOLDN: length 13.8
  TOP w0.152: IC13.AJ1 88.67,48.37 v1(88.75,48.29) ; U11.7 v1(91.19,57.21)
  BOTTOM w0.152: v1(88.75,48.29) 88.24,48.79 88.24,49.49 88.24,54.77 90.27,56.81 90.78,56.81 v1(91.19,57.21) 91.19,58.03 R170.1
SFC_WPN: length 13.2
  TOP w0.152: v1(92.46,48.42) 90.4,48.42 90.02,48.81 87.02,48.81 86.58,48.37 IC13.AJ3 ; v1(92.46,49.97) U11.3 v1(92.46,53)
  BOTTOM w0.152: R168.1 R169.2 v1(92.46,53) ; v1(92.46,49.97) v1(92.46,48.42)
SPDIF_OUT\G: length 3.7
  TOP w0.152: XS7.3 31.75,120.15 R81.2
STBY_PWROFF\G: length 337
  TOP w0.381: R82.1 v1(152.02,69.22) ; v1(8.74,60.11) 7.98,59.35 7.98,20.36 12.42,15.91 12.42,4.61 14.28,2.75 v1(34.84,2.75) ; v1(50.78,83.22) 50.78,83.86 49.25,85.38 v1(48.87,85.38) ; IC13.C12 v2(79.55,27.17)
  BOTTOM w0.381: v1(152.02,69.22) 129.17,69.22 113.77,84.62 113.77,94.02 112.62,95.16 90.02,95.16 78.08,83.22 v1(50.78,83.22) ; R89.1 34.84,5.16 v1(34.84,2.75) 72.92,2.75 79.57,9.4 79.57,18.83 80.81,20.08 80.81,25.91 R251.1 79.96,26.22 79.55,26.63 v2(79.55,27.17) ; R68.2 R69.2 v1(8.74,60.11) 8.74,64.68 18.77,74.71 29.95,74.71 36.17,80.94 36.17,85.25 37.82,86.91 46.33,86.91 46.97,86.27 R61.1 v1(48.87,85.38)
SYNTH_VCO_VDD1P2: length 5.3
  TOP w0.203: U18.36 128.43,42.81 C325.2 129.79,41.03 130.02,40.8 FB3.2
SYNTH_VDD1P2: length 5
  TOP w0.203: FB2.2 130.02,42.07 129.79,42.3 C329.2 129.13,42.71 128.64,43.21 U18.37
TCK_ICE\G: length 2.7
  TOP w0.127: IC13.B14 77.96,26.36 77.96,25.76
  TOP w0.152: R249.1 78.46,25.06 77.96,25.56 77.96,25.76
TDI: length 2.7
  TOP w0.152: R344.2 R349.1 118.61,48.01 U18.3
TDI_ICE\G: length 4.1
  TOP w0.152: R245.1 79.03,25.29 IC13.A13
TDO_ICE\G: length 3.4
  TOP w0.127: IC13.C14 77.55,27.32 77.16,26.93 77.16,25.4
  TOP w0.152: 77.16,25.4 77.16,24.55 R244.1
TMS_ICE\G: length 4
  TOP w0.152: R248.1 77.89,24.85 77.55,25.18 IC13.A14
TRST_ICE\G: length 2.9
  TOP w0.152: IC13.B13 78.35,26.62 79.45,25.52 79.45,24.89 79.6,24.74 R250.1
TX+_PHY0\G: length 19.4
  TOP w0.152: TR2.1 15.44,96.9 17.09,95.25 17.09,94.36 17.53,93.93 23.11,93.93 23.24,93.8 23.24,92.51 23.06,92.33 22.95,92.33 v1(22.67,92.61) 22.42,92.35 22.1,92.35 21.82,92.07 21.82,90.12 R129.2
  BOTTOM w0.152: U17.1 v1(22.67,92.61) 22.42,92.35 21.31,92.35 R310.2
TX-_PHY0\G: length 19
  TOP w0.152: TR2.3 19.05,96.9 17.4,95.25 17.4,94.49 17.65,94.23 23.24,94.23 23.55,93.93 23.55,92.38 23.19,92.02 22.9,92.02 v1(22.67,91.8) 22.42,92.05 22.23,92.05 22.12,91.95 22.12,90.12 R128.2
  BOTTOM w0.152: U17.6 v1(22.67,91.8) 22.42,92.05 21.31,92.05 R308.2
TX_2G_CORE_VDD1P2: length 14.9
  TOP w0.203: v1(121.27,40.06) 121.64,40.43 U18.21 121.64,42.14 121.84,42.34 124.69,42.34 124.84,42.2 U18.29 124.84,40.7 v1(125,40.53)
  BOTTOM w0.406: v1(125,40.53) 125,40.59 124.95,40.64 124.95,41.12 125.39,41.57 C374.1 ; v1(121.27,40.06) 120.5,39.29 C241.1 117.73,39 C249.2 R318.2
TXD0_RMII0\G: length 40.3
  TOP w0.152: 51.31,56.43 R235.2 51.31,57.29 48.82,59.78 44.35,59.78 43.59,59.78 39.14,64.22 39.14,66.21 36.3,69.05 36.3,71.15 30.02,77.43 25.7,77.43 25.37,77.76 IC8.24
TXD1_RMII0\G: length 41.2
  TOP w0.152: IC8.25 26.4,81.05 26.77,80.68 26.77,78.9 27.94,77.74 30.15,77.74 36.6,71.28 36.6,69.18 39.45,66.33 39.45,64.35 43.72,60.08 44.22,60.08 50.55,60.08 53.47,57.16 R236.2
TXEN_RMII0: length 39.6
  TOP w0.152: 49.15,56.43 R234.2 49.15,58.69 48.36,59.47 44.47,59.47 44.47,59.47 43.46,59.47 38.84,64.1 38.84,66.08 35.99,68.93 35.99,71.03 29.89,77.13 25.25,77.13 24.87,77.5 IC8.23
TXG_0: length 2.3
  TOP w0.254: R334.2 L31.2 C228.1
TXG_0_SW_IN: length 3.2
  TOP w0.254: R336.2 130.53,31.03 U21.1 C332.1
TXG_1: length 2.3
  TOP w0.254: R252.2 120.46,36.98 L26.2 C327.1
TXG_1_SW_IN: length 2.2
  TOP w0.254: R345.2 120.63,30.52 U19.3 120.63,32.42 C373.1
UART0_RXD\G: length 20.9
  TOP w0.127: IC13.AU25 68.34,55.18 68.34,55.75 68.21,55.89
  TOP w0.152: 68.21,55.89 67.74,56.35 67.74,70.32 65.99,72.07 R485.1
UART0_TXD\G: length 21.4
  TOP w0.152: IC13.AV25 68.61,55.71 68.61,55.92 68.05,56.48 68.05,71.28 65.99,73.34 R479.1
USB0_PWREN\G: length 61.4
  TOP w0.254: v1(67.28,67.98) 67.31,67.96 67.31,55.41 IC13.AU26
  TOP w0.381: R301.1 R103.2 ; R103.2 v1(101.1,92.58) ; R103.2 R253.1
  BOTTOM w0.381: v1(67.28,67.98) 71.1,67.98 87.99,84.87 92.94,84.87 100.65,92.58 v1(101.1,92.58)
USB1_PWREN\G: length 66.7
  TOP w0.127: 66.95,56.77 66.95,55.02 67.6,54.38 68.34,54.38 IC13.AT25
  TOP w0.152: 66.95,56.77 66.95,67.22 66.78,67.4 v1(66.78,68.49)
  BOTTOM w0.152: v1(66.78,68.49) 67.71,68.49 88.16,88.94 95.73,88.94 100.05,93.26 R107.2 R329.1 R322.1
USB1D_DM\G: length 115.3
  TOP w0.203: IC13.AV29 65.53,55.59 65.53,56.86 arc(65.49,57.08) 65.36,57.27 arc(65.22,57.47) 65.18,57.72 65.18,61.94 arc(65,62.37) 64.57,62.55 64.47,62.55 arc(64.32,62.61) 64.26,62.75 v1(64.26,62.93) ; U1.21 99.81,72.58 99.88,72.52 99.88,68.64 arc(99.84,68.42) v1(99.71,68.24) arc(99.81,68.1) 99.84,67.93 99.84,67.41 arc(100.05,66.9) 100.56,66.69 139.83,66.69 arc(140.4,66.57) 140.89,66.25 141.19,65.95 153.2,53.94 153.45,53.68 arc(154.02,53.31) 154.69,53.17 155.21,53.17 arc(155.28,53.17) 155.34,53.16 arc(155.54,53.09) R604.2
  BOTTOM w0.203: v1(64.26,62.93) 64.26,62.85 arc(64.35,62.64) 64.57,62.55 95.23,62.55 arc(95.54,62.61) 95.8,62.79 99.71,66.69 arc(99.92,67) 99.99,67.37 99.99,67.96 arc(99.91,68.15) v1(99.71,68.24)
USB1D_DP\G: length 115.6
  TOP w0.203: v1(64.26,61.96) 64.35,62.05 arc(64.45,62.12) 64.57,62.14 arc(64.71,62.08) 64.77,61.94 64.77,57.72 arc(64.85,57.32) 65.07,56.98 arc(65.11,56.93) 65.12,56.86 65.12,55.48 arc(65.18,55.22) 65.32,55 IC13.AU29 ; R603.2 155.7,53.86 arc(155.62,53.66) 155.42,53.58 154.69,53.58 arc(154.17,53.68) 153.74,53.97 153.48,54.23 142.15,65.57 141.48,66.23 141.18,66.53 arc(140.56,66.95) 139.83,67.09 100.56,67.09 arc(100.34,67.18) 100.25,67.41 100.25,67.75 arc(100.29,67.99) 100.43,68.19 v1(100.48,68.24) arc(100.33,68.45) 100.29,68.69 100.29,72.55 100.31,72.58 U1.22
  BOTTOM w0.203: v1(64.26,61.96) arc(64.43,62.08) 64.62,62.14 arc(64.65,62.14) 64.69,62.14 95.23,62.14 arc(95.69,62.23) 96.09,62.5 100,66.41 arc(100.3,66.85) 100.4,67.37 100.4,68.05 arc(100.42,68.15) v1(100.48,68.24)
USB_HUB_RST\G: length 68.7
  TOP w0.152: R363.2 57.76,61.63 58.27,62.14 v1(58.4,62.14) ; U1.37 v1(101.31,80.94)
  BOTTOM w0.152: R589.2 101.19,81.06 v1(101.31,80.94) 101.7,81.32 C418.1 102.23,80.91 102.46,80.68 103.05,80.68 104.62,79.11 104.62,67.6 97.89,60.87 62.66,60.87 61.39,62.14 v1(58.4,62.14)
USB_HUB_XI: length 8.2
  TOP w0.152: U2.1 88.31,78.04 90.16,78.04 C422.1 91.96,77.51 R591.1 92.01,77.51 93.36,76.16 U1.10
USB_HUB_XO: length 4.4
  TOP w0.152: U2.3 89.62,75.35 C423.1 R590.2 R591.2
USBHUB1_DM: length 56.7
  TOP w0.203: R592.2 107.29,73.96 109.78,73.96 arc(110.6,74.13) 111.3,74.59 113.6,76.89 arc(114,77.49) 114.14,78.2 114.14,104.33 arc(114.25,104.89) 114.57,105.37 118.11,108.91 arc(118.58,109.61) 118.75,110.45 118.75,112.75 arc(118.53,113.27) 118.01,113.49 117.65,113.49 arc(117.48,113.56) v1(117.41,113.73)
  BOTTOM w0.203: U3.3 v1(117.41,113.73) arc(117.48,113.56) 117.65,113.49 124.19,113.49 arc(124.76,113.73) XS5.2
USBHUB1_DP: length 56.7
  TOP w0.203: R593.2 107.29,74.37 109.78,74.37 arc(110.45,74.5) 111.02,74.88 113.31,77.18 arc(113.62,77.65) 113.73,78.2 113.73,104.33 arc(113.88,105.05) 114.28,105.66 117.82,109.19 arc(118.2,109.77) 118.34,110.45 118.34,112.75 arc(118.24,112.98) 118.01,113.08 117.65,113.08 arc(117.48,113.01) v1(117.41,112.84)
  BOTTOM w0.203: U3.4 v1(117.41,112.84) arc(117.48,113.01) 117.65,113.08 121.8,113.08 arc(122.08,112.96) 122.2,112.67 122.2,112.51 arc(122.61,112.1) 123.02,112.51 123.02,112.67 arc(123.13,112.96) 123.42,113.08 124.22,113.08 arc(124.77,112.85) XS5.3
USBHUB1_FLG: length 50.7
  TOP w0.152: R606.2 122.92,104.72 v1(123.44,104.72) U5.2 ; v1(110.26,104.72) 110.41,104.57 110.41,85.08 109.75,84.42 97.64,84.42 96.81,83.59 U1.46
  BOTTOM w0.152: v1(110.26,104.72) v1(123.44,104.72)
USBHUB1_PWREN: length 50.8
  TOP w0.152: R605.2 122.84,105.37 v1(123.44,105.37) U5.1 ; U1.45 97.31,83.5 97.93,84.11 109.88,84.11 110.72,84.95 110.72,105.22 v1(110.57,105.37)
  BOTTOM w0.152: v1(110.57,105.37) v1(123.44,105.37)
USBHUB1_VBUS: length 0.7
  BOTTOM w0.406: C424.1 v1(127.66,104.12)
USBHUB2_DM: length 85.2
  TOP w0.203: v1(111.8,78.1) 111.79,78.11 arc(111.6,78.24) 111.38,78.28 111.07,78.28 arc(110.59,78.19) 110.18,77.91 109.03,76.76 108.98,76.71 arc(108.47,76.37) 107.87,76.25 107.29,76.25 arc(107.03,76.14) R594.2 ; R604.1 arc(156.79,53.27) 157.09,53.39 157.38,53.39 arc(157.66,53.33) v1(157.91,53.17) arc(158.1,53.3) 158.34,53.35 159.91,53.35 arc(160.46,53.12) XS1.2
  BOTTOM w0.203: U4.6 158.43,39.72 arc(158.76,39.86) 158.9,40.19 158.9,40.77 arc(158.82,40.95) 158.64,41.03 arc(158.45,41.11) 158.37,41.3 158.37,41.58 arc(158.45,41.77) 158.64,41.84 arc(158.82,41.92) 158.9,42.11 158.9,52.88 arc(158.76,53.21) 158.43,53.35 158.34,53.35 arc(158.1,53.3) v1(157.91,53.17) arc(157.71,53.3) 157.48,53.35 arc(157.08,53.51) 156.92,53.91 156.92,57.06 arc(156.85,57.44) 156.63,57.75 148.3,66.09 147.9,66.49 arc(147.47,66.78) 146.97,66.88 128.65,66.88 arc(128.01,67) 127.46,67.37 117.08,77.75 116.95,77.88 arc(116.51,78.18) 115.98,78.28 112.23,78.28 arc(112,78.24) v1(111.8,78.1)
USBHUB2_DP: length 85.2
  TOP w0.203: R595.2 arc(107.03,76.76) 107.29,76.66 107.87,76.66 arc(108.32,76.74) 108.69,76.99 108.74,77.04 109.9,78.2 arc(110.44,78.56) 111.07,78.69 111.37,78.69 arc(111.6,78.73) v1(111.8,78.87) ; R603.1 arc(156.8,53.93) 157.11,53.8 157.58,53.8 arc(157.76,53.83) v1(157.91,53.93) arc(158.1,53.8) 158.34,53.76 159.87,53.76 arc(160.45,54) XS1.3
  BOTTOM w0.203: U4.1 159.78,39.72 arc(159.45,39.86) 159.31,40.19 159.31,52.88 arc(159.05,53.5) 158.43,53.76 158.34,53.76 arc(158.1,53.8) v1(157.91,53.93) arc(157.71,53.8) 157.48,53.76 arc(157.37,53.8) 157.33,53.91 157.33,57.06 arc(157.22,57.59) 156.92,58.04 156.84,58.12 156.66,58.3 148.18,66.78 arc(147.63,67.15) 146.97,67.28 128.65,67.28 arc(128.16,67.38) 127.75,67.66 117.24,78.16 arc(116.66,78.55) 115.98,78.69 112.23,78.69 arc(112,78.73) v1(111.8,78.87)
USBHUB2_FLG: length 92.7
  TOP w0.152: v1(150.6,41.19) 152.52,41.19 152.6,41.11 152.6,41.11 153.48,40.22 U6.2 153.48,37.32 R609.2 ; U1.44 v1(97.81,80.92)
  BOTTOM w0.152: v1(97.81,80.92) 98.93,82.04 104.26,82.04 104.93,81.37 104.93,74.29 107.28,71.94 116.82,71.94 125.22,63.54 145.9,63.54 150.98,58.46 150.98,41.57 v1(150.6,41.19)
USBHUB2_PWREN: length 92
  TOP w0.152: R608.2 152.83,37.67 U6.1 152.83,40.44 152.6,40.68 v1(151.13,40.68) ; U1.43 98.31,83.17 v1(98.17,83.31)
  BOTTOM w0.152: v1(151.13,40.68) 151.16,40.68 151.28,40.8 151.28,58.58 146.02,63.84 125.35,63.84 116.94,72.25 107.4,72.25 105.23,74.42 105.23,81.5 104.22,82.51 98.97,82.51 v1(98.17,83.31)
USBHUB2_VBUS: length 3.4
  TOP w0.356: U6.8 v1(152.83,45.07)
  TOP w0.406: C431.1 153.14,48.04
  BOTTOM w0.406: R633.1 152.83,43.84 v1(152.83,45.07)
USBHUB3_DM: length 110.8
  TOP w0.203: R630.1 arc(156.66,25.07) 156.96,25.2 157.48,25.2 arc(157.71,25.15) v1(157.91,25.02) arc(158.1,25.15) 158.34,25.2 159.92,25.2 arc(160.46,24.97) XS10.2 ; v1(108,78.36) arc(107.94,78.48) 107.82,78.54 107.29,78.54 arc(107.03,78.43) R596.2
  BOTTOM w0.203: U4.3 159.82,37.82 arc(159.46,37.67) 159.31,37.31 159.31,25.94 arc(159.09,25.41) 158.57,25.2 158.34,25.2 arc(158.1,25.15) v1(157.91,25.02) 157.89,25.04 arc(157.71,25.16) 157.51,25.2 156.53,25.2 arc(155.82,25.49) 155.52,26.2 155.52,56.53 arc(155.48,56.75) 155.36,56.93 155.33,56.96 147.03,65.25 arc(146.76,65.44) 146.43,65.5 127.45,65.5 arc(126.54,65.69) 125.77,66.2 116.81,75.16 arc(116.3,75.49) 115.7,75.61 112.41,75.61 arc(111.79,75.73) 111.26,76.09 109.01,78.34 arc(108.79,78.48) 108.53,78.54 108.43,78.54 arc(108.19,78.49) v1(108,78.36)
USBHUB3_DP: length 110.9
  TOP w0.203: R597.2 arc(107.03,79.05) 107.29,78.94 107.82,78.94 arc(107.94,78.99) v1(108,79.12) ; R621.1 arc(156.67,25.73) 156.98,25.6 157.48,25.6 arc(157.71,25.65) v1(157.91,25.78) arc(158.1,25.65) 158.34,25.6 159.87,25.6 arc(160.45,25.84) XS10.3
  BOTTOM w0.203: U4.4 158.46,37.82 arc(158.77,37.69) 158.9,37.38 158.9,36.67 arc(158.82,36.48) 158.64,36.41 arc(158.45,36.33) 158.37,36.14 158.37,35.86 arc(158.45,35.67) 158.64,35.59 arc(158.82,35.51) 158.9,35.33 158.9,25.94 arc(158.81,25.7) 158.57,25.6 158.34,25.6 arc(158.1,25.65) v1(157.91,25.78) 157.89,25.76 arc(157.71,25.64) 157.51,25.6 156.53,25.6 arc(156.11,25.78) 155.93,26.2 155.93,56.53 arc(155.86,56.9) 155.64,57.22 147.32,65.54 arc(146.91,65.82) 146.43,65.91 127.45,65.91 arc(126.7,66.06) 126.05,66.49 117.11,75.43 arc(116.46,75.86) 115.7,76.02 112.41,76.02 arc(111.94,76.11) 111.54,76.38 109.37,78.55 109.29,78.63 arc(108.95,78.86) 108.53,78.94 108.43,78.94 arc(108.19,78.99) v1(108,79.12)
USBHUB3_FLG: length 95.7
  TOP w0.152: v1(99.06,83.31) 99.06,83.31 99.31,83.06 U1.41
  BOTTOM w0.152: v1(99.06,83.31) 99.06,83.45 99.43,83.82 99.99,83.82 100.66,83.15 104.45,83.15 105.84,81.75 105.84,74.67 107.66,72.86 117.19,72.86 125.6,64.45 146.28,64.45 151.89,58.84 151.89,37.6 153.39,36.11 R612.2 153.32,34.49 U7.2
USBHUB3_PWREN: length 91.9
  TOP w0.152: U1.40 v1(99.81,83.35)
  BOTTOM w0.152: U7.1 150.9,35.14 150.7,35.34 R611.2 150.7,37.38 151.59,38.26 151.59,58.71 146.15,64.15 125.47,64.15 117.07,72.55 107.53,72.55 105.54,74.55 105.54,81.62 104.32,82.84 100.32,82.84 v1(99.81,83.35)
USBHUB3_VBUS: length 19.1
  TOP w0.406: 144.86,34.96 C435.1 v1(145.57,34.96)
  TOP w0.762: v3(153.52,28.61) 150.34,28.61 146.66,32.3 146.66,33.57 ; v3(153.52,21.72) 153.52,21.75 153.56,21.72 L51.2
  BOTTOM w0.762: v3(153.52,28.61) v3(153.52,21.72)
  vias: v1(145.57,34.2) v1(146.2,34.96) v1(146.2,34.2)
USBHUB4_DM: length 48.3
  TOP w0.203: v1(115.51,113.73) arc(115.58,113.56) 115.75,113.49 arc(116.22,113.29) 116.41,112.83 116.41,110.07 arc(116.31,109.55) 116.01,109.12 113.16,106.27 arc(112.86,105.81) 112.75,105.27 112.75,83.96 arc(112.63,83.33) 112.27,82.8 110.66,81.19 arc(110.25,80.92) 109.76,80.82 107.29,80.82 arc(107.03,80.71) R598.2
  BOTTOM w0.203: U3.1 v1(115.51,113.73) arc(115.44,113.56) 115.27,113.49 108.81,113.49 arc(108.24,113.73) XS4.2
USBHUB4_DP: length 48.3
  TOP w0.203: v1(115.51,112.84) arc(115.58,113.01) 115.75,113.08 arc(115.93,113.01) 116,112.83 116,110.07 arc(115.93,109.71) 115.73,109.4 112.88,106.55 arc(112.48,105.96) 112.34,105.27 112.34,83.96 arc(112.25,83.49) 111.99,83.09 110.38,81.48 arc(110.09,81.29) 109.76,81.23 107.29,81.23 arc(107.03,81.34) R599.2
  BOTTOM w0.203: U3.6 v1(115.51,112.84) arc(115.44,113.01) 115.27,113.08 111.06,113.08 arc(110.77,112.96) 110.65,112.67 110.65,112.48 arc(110.25,112.08) 109.84,112.48 109.84,112.67 arc(109.72,112.96) 109.43,113.08 108.78,113.08 arc(108.23,112.85) XS4.3
